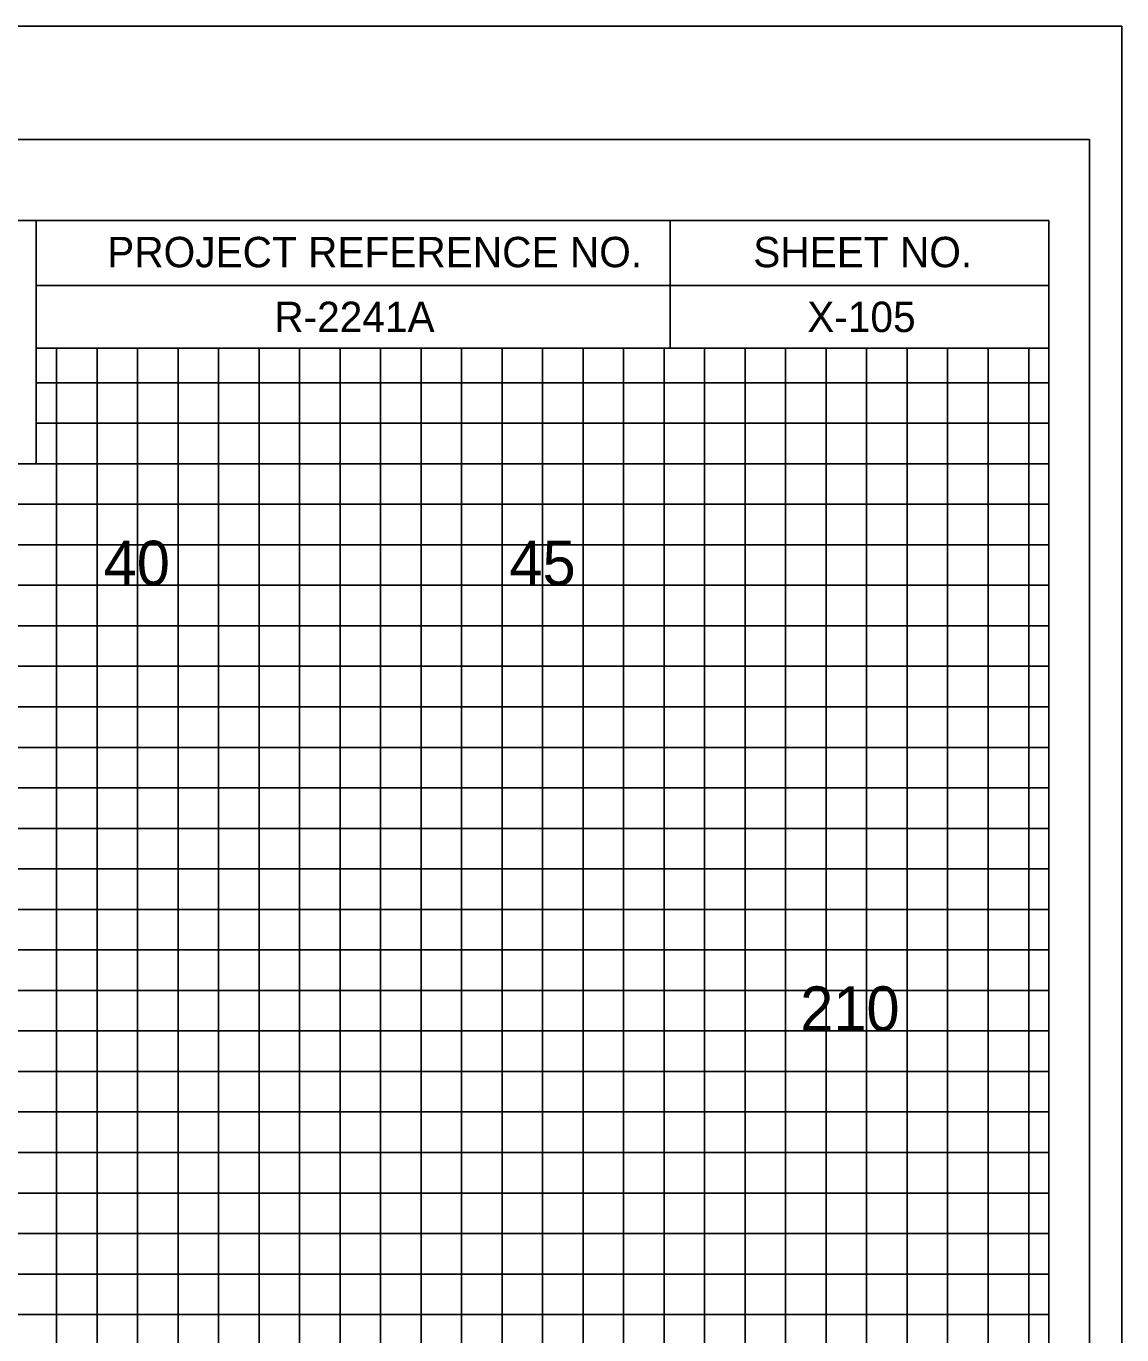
# Model space of a CAD drawing. Extents: x -4 to 103, y -2 to 351.
# Drawn here: x 89.88 to 103.4, y 192.9 to 209.05 of the extents above; entities that cross this region are included whole.
import ezdxf

# ---------------------------------------------------------------- set-up
doc = ezdxf.new("R2010")
doc.units = 0
for name, color, linetype in [('Old_Level_10', 7, 'Continuous'), ('Old_Level_16', 7, 'Continuous'), ('Old_Level_3', 7, 'Continuous'), ('Old_Level_4', 7, 'Continuous'), ('Old_Level_5', 7, 'Continuous'), ('Old_Level_6', 7, 'Continuous'), ('Old_Level_8', 7, 'Continuous'), ('Prop Dimension', 7, 'Continuous'), ('Prop Terminator CELL', 7, 'Continuous'), ('Prop XS Finish Grade', 7, 'Continuous'), ('Prop XS SE Text', 7, 'Continuous')]:
    doc.layers.add(name, color=color, linetype=linetype)

msp = doc.modelspace()

# ---------------------------------------------------------------- linework, layer by layer
at = {"layer": 'Old_Level_10'}
for p, q in [((91.25, 141.65), (91.25, 205.075)), ((93.75, 141.65), (93.75, 205.075)), ((96.25, 141.65), (96.25, 205.075)), ((98.75, 141.65), (98.75, 205.075)), ((101.25, 141.65), (101.25, 205.075)), ((90, 204.15), (102.5, 204.15)), ((0, 201.65), (102.5, 201.65)), ((0, 199.15), (102.5, 199.15)), ((0, 196.65), (102.5, 196.65)), ((0, 194.15), (102.5, 194.15))]:
    msp.add_line(p, q, dxfattribs=at)
at = {"layer": 'Old_Level_3'}
msp.add_line((-3.5, 209.05), (103.4, 209.05), dxfattribs=at)
at = {"layer": 'Old_Level_4'}
for points in [[(90.25, 141.65), (90.25, 205.075), (90.75, 205.075), (90.75, 141.65)], [(91.75, 141.65), (91.75, 205.075), (92.25, 205.075), (92.25, 141.65)], [(92.75, 141.65), (92.75, 205.075), (93.25, 205.075), (93.25, 141.65)], [(94.25, 141.65), (94.25, 205.075), (94.75, 205.075), (94.75, 141.65)], [(95.25, 141.65), (95.25, 205.075), (95.75, 205.075), (95.75, 141.65)], [(96.75, 141.65), (96.75, 205.075), (97.25, 205.075), (97.25, 141.65)], [(97.75, 141.65), (97.75, 205.075), (98.25, 205.075), (98.25, 141.65)], [(99.25, 141.65), (99.25, 205.075), (99.75, 205.075), (99.75, 141.65)], [(100.25, 141.65), (100.25, 205.075)], [(100.25, 205.075), (100.75, 205.075), (100.75, 141.65), (101.75, 141.65), (101.75, 205.075), (102.25, 205.075), (102.25, 141.65)], [(102.5, 203.65), (102.5, 204.65), (90, 204.65)], [(0, 203.15), (102.5, 203.15), (102.5, 203.65), (0, 203.65)], [(0, 202.15), (102.5, 202.15), (102.5, 202.65), (0, 202.65)], [(0, 200.65), (102.5, 200.65), (102.5, 201.15), (0, 201.15)], [(0, 199.65), (102.5, 199.65), (102.5, 200.15), (0, 200.15)], [(0, 198.15), (102.5, 198.15), (102.5, 198.65), (0, 198.65)], [(0, 197.15), (102.5, 197.15), (102.5, 197.65), (0, 197.65)], [(0, 195.65), (102.5, 195.65), (102.5, 196.15), (0, 196.15)], [(0, 194.65), (102.5, 194.65), (102.5, 195.15), (0, 195.15)], [(0, 193.15), (102.5, 193.15), (102.5, 193.65), (0, 193.65)]]:
    msp.add_lwpolyline(points, dxfattribs=at)
at = {"layer": 'Old_Level_5'}
msp.add_lwpolyline([(103.4, 209.05), (-3.5, 209.05), (-3.5, 139.225), (103.4, 139.225)], close=True, dxfattribs=at)
at = {"layer": 'Old_Level_6'}
for p, q in [((90, 206.65), (102.5, 206.65)), ((90, 206.65), (102.5, 206.65)), ((97.825, 205.075), (97.825, 206.65)), ((101.875, 206.65), (101.875, 206.65)), ((102.5, 206.65), (102.5, 206.65)), ((102.5, 205.075), (102.5, 206.65)), ((102.5, 206.65), (102.5, 206.65)), ((102.5, 206.65), (102.5, 206.65)), ((102.5, 205.075), (102.5, 206.65)), ((90, 205.85), (102.5, 205.85)), ((90, 205.075), (102.5, 205.075)), ((99.4, 205.075), (99.4, 205.075)), ((99.4, 205.075), (99.4, 205.075))]:
    msp.add_line(p, q, dxfattribs=at)
for points in [[(102.5, 206.65), (0, 206.65), (0, 141.65), (102.5, 141.65)], [(83.75, 206.65), (90, 206.65), (90, 203.65), (83.75, 203.65)]]:
    msp.add_lwpolyline(points, close=True, dxfattribs=at)
at = {"layer": 'Old_Level_8'}
for points in [[(91.25, 141.65), (91.25, 205.075), (93.75, 205.075), (93.75, 141.65)], [(96.25, 141.65), (96.25, 205.075), (98.75, 205.075), (98.75, 141.65)], [(101.25, 141.65), (101.25, 205.075)], [(90, 204.15), (102.5, 204.15)], [(0, 199.15), (102.5, 199.15), (102.5, 201.65), (0, 201.65)], [(0, 194.15), (102.5, 194.15), (102.5, 196.65), (0, 196.65)]]:
    msp.add_lwpolyline(points, dxfattribs=at)
at = {"layer": 'Prop XS SE Text'}
msp.add_lwpolyline([(103, 207.65), (-2.8, 207.65), (-2.8, 140.65), (103, 140.65)], close=True, dxfattribs=at)

# ---------------------------------------------------------------- texts
at = {"layer": 'Old_Level_16'}
for s, p in [('40', (90.8313, 202.15)), ('45', (95.8399, 202.15))]:
    msp.add_text(s, height=0.55, dxfattribs=at).set_placement(p)
at = {"layer": 'Old_Level_6'}
for s, p in [('PROJECT REFERENCE NO.', (90.875, 206.075)), ('SHEET NO.', (98.85, 206.075))]:
    msp.add_text(s, height=0.375, dxfattribs=at).set_placement(p)
at = {"layer": 'Prop Dimension'}
msp.add_text('X-105', height=0.375, dxfattribs=at).set_placement((99.5164, 205.275))
at = {"layer": 'Prop Terminator CELL'}
msp.add_text('R-2241A', height=0.375, dxfattribs=at).set_placement((92.9378, 205.275))
at = {"layer": 'Prop XS Finish Grade'}
msp.add_text('210', height=0.55, dxfattribs=at).set_placement((99.4296, 196.65))

doc.saveas('drawing.dxf')
